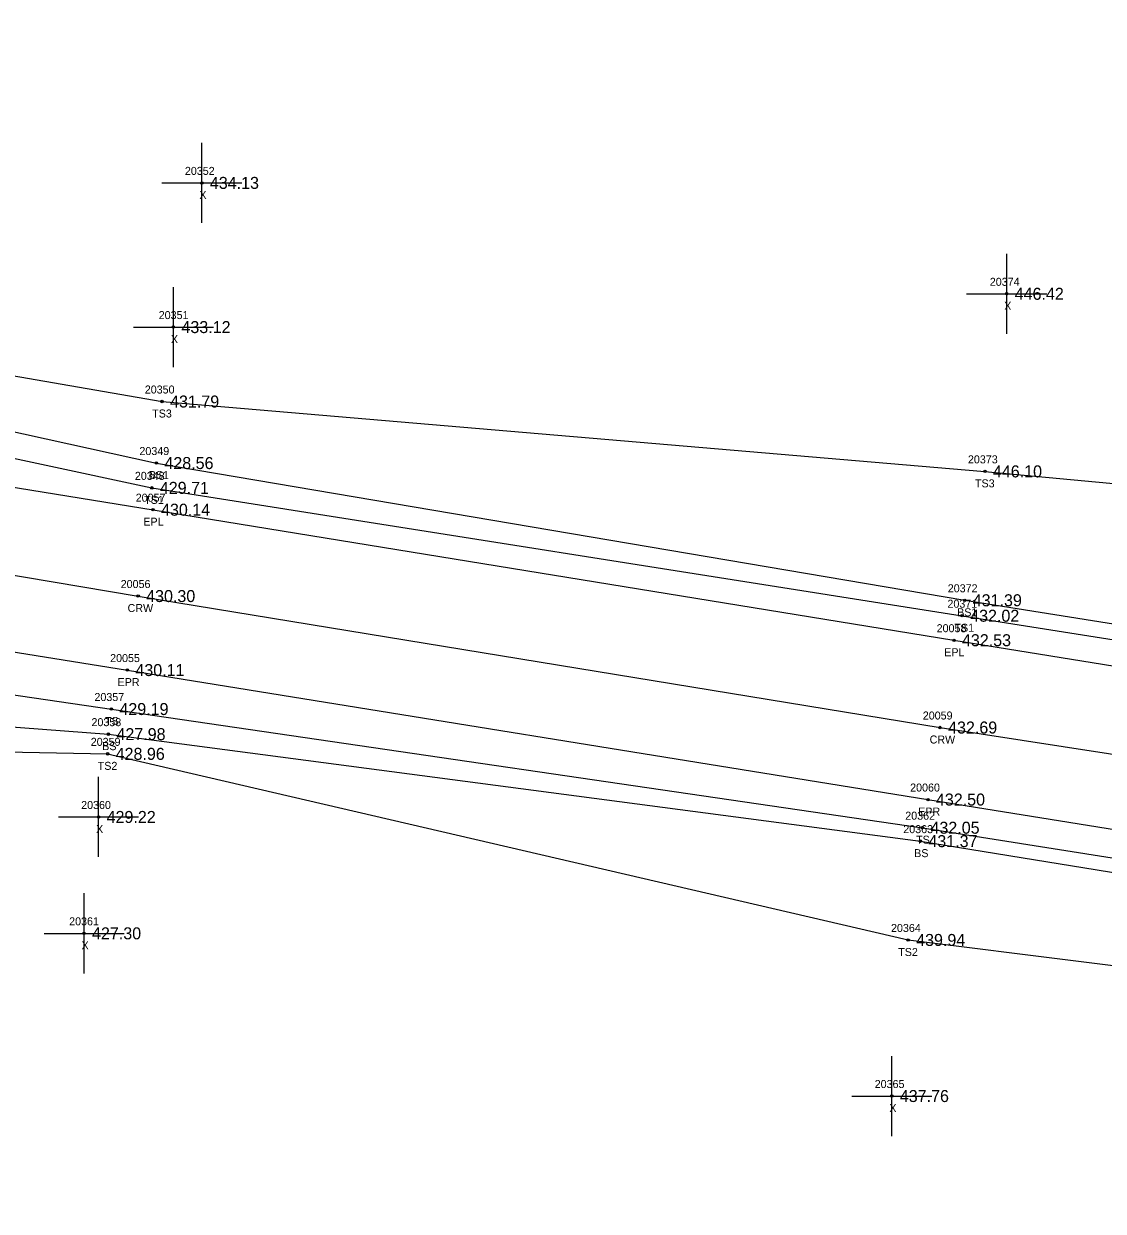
# Model space of a CAD drawing. Extents: x 1613184 to 1614731, y 770859 to 771868.
# Drawn here: x 1614347.3 to 1614482.1, y 771198.3 to 771346.7 of the extents above; entities that cross this region are included whole.
import ezdxf

# ---------------------------------------------------------------- set-up
doc = ezdxf.new("R2010")
doc.units = 0
for name, color, linetype in [('RD_DTM_BkLn1', 7, 'Continuous'), ('RD_DTM_BkLn2', 7, 'Continuous'), ('RD_DTM_BkLn_txCode', 7, 'Continuous'), ('RD_EX_Misc', 7, 'Continuous'), ('RD_EX_Misc_txCode', 7, 'Continuous'), ('RD_EX_Road', 7, 'Continuous'), ('RD_EX_Road_txCode', 7, 'Continuous'), ('RD_EX_TX_Misc_ELEV', 7, 'Continuous'), ('RD_EX_TX_Road_ELEV', 7, 'Continuous'), ('RD_HC_Survey_ELEV', 7, 'Continuous'), ('RD_HC_Survey_txCode', 7, 'Continuous'), ('RD_SMD_Locator', 7, 'Continuous')]:
    doc.layers.add(name, color=color, linetype=linetype)

msp = doc.modelspace()

# ---------------------------------------------------------------- linework, layer by layer
at = {"layer": 'RD_DTM_BkLn1'}
msp.add_lwpolyline([(1613965.11, 771336.88), (1614064.55, 771323.02), (1614163.88, 771306.86), (1614262.51, 771291.89), (1614361.57, 771275.2), (1614461.76, 771258.77), (1614560.71, 771243.49), (1614660.13, 771228.22)], dxfattribs=at)
at = {"layer": 'RD_DTM_BkLn2'}
for points in [[(1613964.19, 771322.73), (1613968.82, 771317.98), (1613995.59, 771312.64), (1614063.18, 771305.5), (1614161.48, 771291.91), (1614259.01, 771275.6), (1614358.23, 771261.08), (1614459.56, 771246.25), (1614559.08, 771230.48), (1614643.28, 771216.31), (1614658.67, 771214.41)], [(1614279.01, 771313.26), (1614281.2, 771317.14), (1614295.57, 771311.48), (1614364.56, 771299.51), (1614467.36, 771290.78), (1614524.89, 771285.37), (1614565.75, 771274.12), (1614650.32, 771251.27)], [(1613942.37, 771316.04), (1613958.6, 771307.1), (1613993.85, 771297.11), (1614061.98, 771289.14), (1614161.12, 771278.24), (1614255.97, 771263.05), (1614304.44, 771258.76), (1614327.58, 771260.25), (1614357.86, 771257.94), (1614459.3, 771244.57), (1614558.63, 771228.44), (1614632.25, 771215.15), (1614636.04, 771209.87), (1614639.16, 771208.8), (1614642.36, 771211.01), (1614643.75, 771203.68), (1614650.35, 771198.32), (1614658.52, 771198.65)], [(1614279.01, 771313.26), (1614280.58, 771310.17), (1614294.3, 771303.5), (1614363.28, 771288.72), (1614464.52, 771272.74), (1614562.89, 771257.17), (1614654.88, 771242.26), (1614663.07, 771241.33)], [(1614281.21, 771312.71), (1614294.52, 771307.09), (1614363.85, 771291.82), (1614464.84, 771274.67), (1614563.17, 771259.04), (1614643.31, 771247.46), (1614652.05, 771248.4), (1614661.41, 771252.06)], [(1614308.13, 771255.96), (1614327.93, 771256.05), (1614357.76, 771255.48), (1614457.77, 771232.22), (1614523.63, 771223.98), (1614557.61, 771219.54), (1614629.42, 771214.32), (1614628.56, 771211.34)]]:
    msp.add_lwpolyline(points, dxfattribs=at)
at = {"layer": 'RD_EX_Misc'}
for p, q in [((1614369.53, 771321.83), (1614369.53, 771331.83)), ((1614364.53, 771326.83), (1614374.53, 771326.83)), ((1614470.08, 771307.97), (1614470.08, 771317.97)), ((1614365.98, 771303.81), (1614365.98, 771313.81)), ((1614465.08, 771312.97), (1614475.08, 771312.97)), ((1614360.98, 771308.81), (1614370.98, 771308.81)), ((1614356.63, 771242.59), (1614356.63, 771252.59)), ((1614351.63, 771247.59), (1614361.63, 771247.59)), ((1614354.81, 771228.05), (1614354.81, 771238.05)), ((1614349.81, 771233.05), (1614359.81, 771233.05)), ((1614455.73, 771207.72), (1614455.73, 771217.72)), ((1614450.73, 771212.72), (1614460.73, 771212.72))]:
    msp.add_line(p, q, dxfattribs=at)
at = {"layer": 'RD_EX_Road'}
for points in [[(1613966.21, 771346.72), (1614065.91, 771332.61), (1614166, 771316.74), (1614252.8, 771303.53), (1614264.27, 771301.76), (1614271.95, 771300.8), (1614363.43, 771285.99), (1614463.49, 771269.68), (1614562.24, 771253.72), (1614661.91, 771238.32)], [(1613963.41, 771324.71), (1614062.98, 771312.73), (1614162.48, 771297.04), (1614260.87, 771281.9), (1614360.23, 771265.95), (1614460.24, 771249.77), (1614559.17, 771233.87), (1614658.84, 771218.34)]]:
    msp.add_lwpolyline(points, dxfattribs=at)
at = {"layer": 'RD_SMD_Locator'}
for centre in [(1614369.53, 771326.83), (1614470.08, 771312.97), (1614365.98, 771308.81), (1614364.56, 771299.51), (1614363.85, 771291.82), (1614467.36, 771290.78), (1614363.28, 771288.72), (1614363.43, 771285.99), (1614361.57, 771275.2), (1614464.84, 771274.67), (1614464.52, 771272.74), (1614463.49, 771269.68), (1614360.23, 771265.95), (1614358.23, 771261.08), (1614461.76, 771258.77), (1614357.86, 771257.94), (1614357.76, 771255.48), (1614460.24, 771249.77), (1614356.63, 771247.59), (1614459.56, 771246.25), (1614459.3, 771244.57), (1614354.81, 771233.05), (1614457.77, 771232.22), (1614455.73, 771212.72)]:
    msp.add_circle(centre, 0.15, dxfattribs=at)

# ---------------------------------------------------------------- texts
at = {"layer": 'RD_DTM_BkLn_txCode'}
for s, p in [('20350', (1614362.4, 771300.51)), ('TS3', (1614363.32, 771297.51)), ('20349', (1614361.73, 771292.82)), ('20373', (1614465.24, 771291.78)), ('20348', (1614361.16, 771289.72)), ('BS1', (1614362.9, 771289.82)), ('TS3', (1614466.12, 771288.78)), ('TS1', (1614362.32, 771286.72)), ('20372', (1614462.72, 771275.67)), ('20371', (1614462.68, 771273.74)), ('BS1', (1614463.89, 771272.67)), ('TS1', (1614463.56, 771270.74)), ('20357', (1614356.11, 771262.08)), ('20358', (1614355.74, 771258.94)), ('TS', (1614357.44, 771259.08)), ('20359', (1614355.65, 771256.48)), ('BS', (1614357.08, 771255.94)), ('TS2', (1614356.52, 771253.48)), ('20362', (1614457.41, 771247.25)), ('20363', (1614457.16, 771245.57)), ('TS', (1614458.76, 771244.25)), ('BS', (1614458.52, 771242.57)), ('20364', (1614455.63, 771233.22)), ('TS2', (1614456.53, 771230.22))]:
    msp.add_text(s, height=1, dxfattribs=at).set_placement(p)
at = {"layer": 'RD_EX_Misc_txCode'}
for s, p in [('20352', (1614367.41, 771327.83)), ('X', (1614369.22, 771324.83)), ('20374', (1614467.97, 771313.97)), ('X', (1614469.77, 771310.97)), ('20351', (1614364.14, 771309.81)), ('X', (1614365.66, 771306.81)), ('20360', (1614354.45, 771248.59)), ('X', (1614356.31, 771245.59)), ('20361', (1614352.95, 771234.05)), ('X', (1614354.5, 771231.05)), ('20365', (1614453.59, 771213.72)), ('X', (1614455.42, 771210.72))]:
    msp.add_text(s, height=1, dxfattribs=at).set_placement(p)
at = {"layer": 'RD_EX_Road_txCode'}
for s, p in [('20057', (1614361.27, 771286.99)), ('EPL', (1614362.22, 771283.99)), ('20058', (1614461.33, 771270.68)), ('EPL', (1614462.28, 771267.68)), ('20055', (1614358.07, 771266.95)), ('EPR', (1614359, 771263.95)), ('20060', (1614458.02, 771250.77)), ('EPR', (1614459.02, 771247.77))]:
    msp.add_text(s, height=1, dxfattribs=at).set_placement(p)
at = {"layer": 'RD_EX_TX_Misc_ELEV'}
for s, p in [('434.13', (1614370.53, 771326.08)), ('446.42', (1614471.08, 771312.22)), ('433.12', (1614366.98, 771308.06)), ('431.79', (1614365.56, 771298.76)), ('428.56', (1614364.85, 771291.07)), ('446.10', (1614468.36, 771290.03)), ('429.71', (1614364.28, 771287.97)), ('431.39', (1614465.84, 771273.92)), ('432.02', (1614465.52, 771271.99)), ('429.19', (1614359.23, 771260.33)), ('427.98', (1614358.86, 771257.19)), ('428.96', (1614358.76, 771254.73)), ('429.22', (1614357.63, 771246.84)), ('432.05', (1614460.56, 771245.5)), ('431.37', (1614460.3, 771243.82)), ('427.30', (1614355.81, 771232.3)), ('439.94', (1614458.77, 771231.47)), ('437.76', (1614456.73, 771211.97))]:
    msp.add_text(s, height=1.5, dxfattribs=at).set_placement(p)
at = {"layer": 'RD_EX_TX_Road_ELEV'}
for s, p in [('430.14', (1614364.43, 771285.24)), ('432.53', (1614464.49, 771268.93)), ('430.11', (1614361.23, 771265.2)), ('432.50', (1614461.24, 771249.02))]:
    msp.add_text(s, height=1.5, dxfattribs=at).set_placement(p)
at = {"layer": 'RD_HC_Survey_ELEV'}
for s, p in [('430.30', (1614362.57, 771274.45)), ('432.69', (1614462.76, 771258.02))]:
    msp.add_text(s, height=1.5, dxfattribs=at).set_placement(p)
at = {"layer": 'RD_HC_Survey_txCode'}
for s, p in [('20056', (1614359.39, 771276.2)), ('CRW', (1614360.25, 771273.2)), ('20059', (1614459.6, 771259.77)), ('CRW', (1614460.45, 771256.77))]:
    msp.add_text(s, height=1, dxfattribs=at).set_placement(p)

doc.saveas('drawing.dxf')
